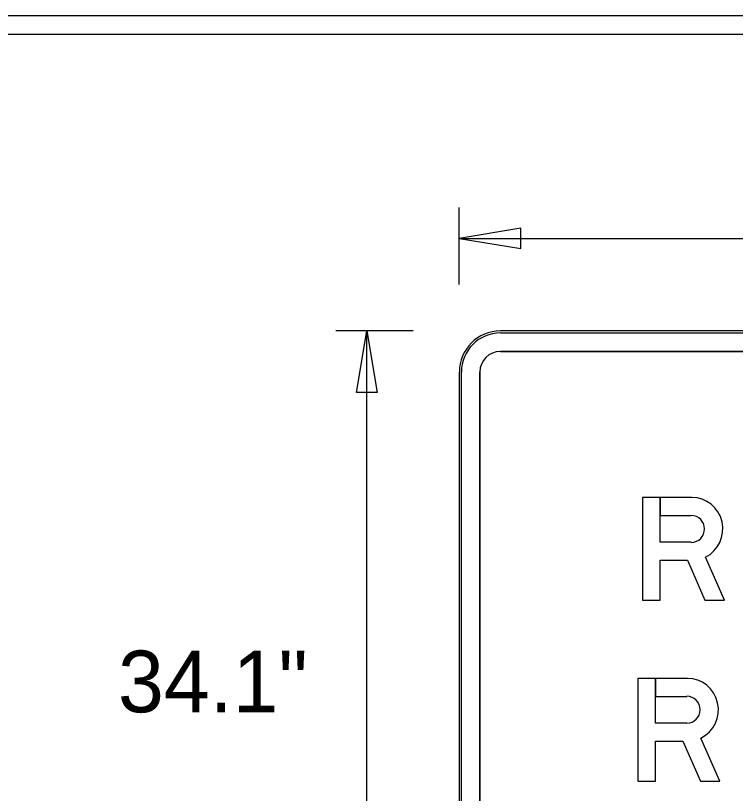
# Model space of a CAD drawing. Extents: x 17890628 to 17890844, y 17897693 to 17898031.
# Drawn here: x 17890803.98 to 17890814.19, y 17897946.34 to 17897957.37 of the extents above; entities that cross this region are included whole.
import ezdxf

# ---------------------------------------------------------------- set-up
doc = ezdxf.new("R2010")
doc.units = 0
for name, color, linetype in [('GSBWFill', 7, 'Continuous'), ('GSColorFill', 7, 'Continuous'), ('GSDims', 7, 'Continuous'), ('GSOutline', 7, 'Continuous'), ('SheetLinesMisc2_dp', 7, 'Continuous')]:
    doc.layers.add(name, color=color, linetype=linetype)

msp = doc.modelspace()

# ---------------------------------------------------------------- linework, layer by layer
at = {"layer": 'GSBWFill'}
for p, q in [((17890823.688, 17897952.897), (17890810.855, 17897952.897)), ((17890810.855, 17897952.606), (17890823.688, 17897952.606)), ((17890810.271, 17897952.314), (17890810.271, 17897939.481)), ((17890810.563, 17897939.481), (17890810.563, 17897952.314))]:
    msp.add_line(p, q, dxfattribs=at)
for points in [[(17890813.563, 17897949.899), (17890813.121, 17897949.899), (17890813.121, 17897950.535), (17890812.869, 17897950.535), (17890812.869, 17897949.077)], [(17890813.571, 17897950.535), (17890813.121, 17897950.535), (17890813.121, 17897950.28), (17890813.563, 17897950.28)], [(17890812.869, 17897949.077), (17890813.121, 17897949.077), (17890813.121, 17897949.643), (17890813.508, 17897949.643), (17890813.757, 17897949.077), (17890814.033, 17897949.077), (17890813.763, 17897949.689)], [(17890813.5, 17897947.332), (17890813.057, 17897947.332), (17890813.057, 17897947.968), (17890812.806, 17897947.968), (17890812.806, 17897946.51)], [(17890813.508, 17897947.968), (17890813.057, 17897947.968), (17890813.057, 17897947.713), (17890813.5, 17897947.713)], [(17890812.806, 17897946.51), (17890813.057, 17897946.51), (17890813.057, 17897947.077), (17890813.445, 17897947.077), (17890813.694, 17897946.51), (17890813.97, 17897946.51), (17890813.7, 17897947.122)]]:
    msp.add_lwpolyline(points, dxfattribs=at)
for radius in [0.583, 0.292]:
    msp.add_arc((17890810.855, 17897952.314), radius, 90, 180, dxfattribs=at)
for centre, major_axis, start_param in [((17890813.571, 17897950.089), (0, 0.446), 3.595687), ((17890813.563, 17897950.089), (0, 0.191), 3.141593), ((17890813.508, 17897947.523), (0, 0.446), 3.595687), ((17890813.5, 17897947.523), (0, 0.191), 3.141593)]:
    msp.add_ellipse(centre, major_axis=major_axis, ratio=0.985, start_param=start_param, end_param=6.283185, dxfattribs=at)
at = {"layer": 'GSColorFill'}
for p, q in [((17890823.688, 17897952.897), (17890810.855, 17897952.897)), ((17890823.688, 17897952.897), (17890810.855, 17897952.897)), ((17890823.688, 17897952.897), (17890810.855, 17897952.897)), ((17890810.855, 17897952.868), (17890823.688, 17897952.868)), ((17890810.855, 17897952.606), (17890823.688, 17897952.606)), ((17890810.271, 17897952.314), (17890810.271, 17897939.481)), ((17890810.271, 17897952.314), (17890810.271, 17897939.481)), ((17890810.271, 17897952.314), (17890810.271, 17897939.481)), ((17890810.301, 17897939.481), (17890810.301, 17897952.314)), ((17890810.563, 17897939.481), (17890810.563, 17897952.314))]:
    msp.add_line(p, q, dxfattribs=at)
for points in [[(17890813.563, 17897949.899), (17890813.121, 17897949.899), (17890813.121, 17897950.535), (17890812.869, 17897950.535), (17890812.869, 17897949.077)], [(17890813.571, 17897950.535), (17890813.121, 17897950.535), (17890813.121, 17897950.28), (17890813.563, 17897950.28)], [(17890812.869, 17897949.077), (17890813.121, 17897949.077), (17890813.121, 17897949.643), (17890813.508, 17897949.643), (17890813.757, 17897949.077), (17890814.033, 17897949.077), (17890813.763, 17897949.689)], [(17890813.5, 17897947.332), (17890813.057, 17897947.332), (17890813.057, 17897947.968), (17890812.806, 17897947.968), (17890812.806, 17897946.51)], [(17890813.508, 17897947.968), (17890813.057, 17897947.968), (17890813.057, 17897947.713), (17890813.5, 17897947.713)], [(17890812.806, 17897946.51), (17890813.057, 17897946.51), (17890813.057, 17897947.077), (17890813.445, 17897947.077), (17890813.694, 17897946.51), (17890813.97, 17897946.51), (17890813.7, 17897947.122)]]:
    msp.add_lwpolyline(points, dxfattribs=at)
for radius in [0.583, 0.583, 0.583, 0.554, 0.292]:
    msp.add_arc((17890810.855, 17897952.314), radius, 90, 180, dxfattribs=at)
for centre, major_axis, start_param in [((17890813.571, 17897950.089), (0, 0.446), 3.595687), ((17890813.563, 17897950.089), (0, 0.191), 3.141593), ((17890813.508, 17897947.523), (0, 0.446), 3.595687), ((17890813.5, 17897947.523), (0, 0.191), 3.141593)]:
    msp.add_ellipse(centre, major_axis=major_axis, ratio=0.985, start_param=start_param, end_param=6.283185, dxfattribs=at)
at = {"layer": 'GSDims'}
for p, q in [((17890810.271, 17897953.554), (17890810.271, 17897954.647)), ((17890810.271, 17897954.21), (17890824.272, 17897954.21)), ((17890809.615, 17897952.897), (17890808.521, 17897952.897)), ((17890808.959, 17897942.952), (17890808.959, 17897952.897))]:
    msp.add_line(p, q, dxfattribs=at)
for points in [[(17890810.271, 17897954.21), (17890811.146, 17897954.064), (17890811.146, 17897954.356)], [(17890808.959, 17897952.897), (17890809.105, 17897952.022), (17890808.813, 17897952.022)]]:
    msp.add_lwpolyline(points, close=True, dxfattribs=at)
at = {"layer": 'GSOutline'}
for p, q in [((17890823.688, 17897952.897), (17890810.855, 17897952.897)), ((17890823.688, 17897952.606), (17890810.855, 17897952.606)), ((17890810.271, 17897952.314), (17890810.271, 17897939.481)), ((17890810.563, 17897952.314), (17890810.563, 17897939.481)), ((17890813.563, 17897949.899), (17890813.121, 17897949.899)), ((17890813.5, 17897947.332), (17890813.057, 17897947.332))]:
    msp.add_line(p, q, dxfattribs=at)
for points in [[(17890813.571, 17897950.535), (17890812.869, 17897950.535), (17890812.869, 17897949.077), (17890813.121, 17897949.077), (17890813.121, 17897949.643), (17890813.508, 17897949.643)], [(17890813.121, 17897949.899), (17890813.121, 17897950.28), (17890813.563, 17897950.28)], [(17890813.508, 17897949.643), (17890813.757, 17897949.077), (17890814.033, 17897949.077), (17890813.763, 17897949.689)], [(17890813.508, 17897947.968), (17890812.806, 17897947.968), (17890812.806, 17897946.51), (17890813.057, 17897946.51), (17890813.057, 17897947.077), (17890813.445, 17897947.077)], [(17890813.057, 17897947.332), (17890813.057, 17897947.713), (17890813.5, 17897947.713)], [(17890813.445, 17897947.077), (17890813.694, 17897946.51), (17890813.97, 17897946.51), (17890813.7, 17897947.122)]]:
    msp.add_lwpolyline(points, dxfattribs=at)
for radius in [0.583, 0.292]:
    msp.add_arc((17890810.855, 17897952.314), radius, 90, 180, dxfattribs=at)
for centre, major_axis, start_param in [((17890813.571, 17897950.089), (0, 0.446), 3.595687), ((17890813.563, 17897950.089), (0, 0.191), 3.141593), ((17890813.508, 17897947.523), (0, 0.446), 3.595687), ((17890813.5, 17897947.523), (0, 0.191), 3.141593)]:
    msp.add_ellipse(centre, major_axis=major_axis, ratio=0.985, start_param=start_param, end_param=6.283185, dxfattribs=at)
at = {"layer": 'SheetLinesMisc2_dp'}
for p, q in [((17890705.5, 17897957.37), (17890839.233, 17897957.37)), ((17890793.11, 17897957.108), (17890838.594, 17897957.108))]:
    msp.add_line(p, q, dxfattribs=at)

# ---------------------------------------------------------------- texts
at = {"layer": 'GSDims'}
msp.add_text('34.1"', height=0.875, dxfattribs=at).set_placement((17890805.429, 17897947.487))

doc.saveas('drawing.dxf')
